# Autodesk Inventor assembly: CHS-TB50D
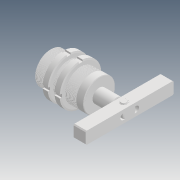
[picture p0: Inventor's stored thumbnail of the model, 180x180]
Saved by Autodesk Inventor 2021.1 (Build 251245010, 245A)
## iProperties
Created: 2019-04
Part Number: CHS-TB50D
Description: STEP AP203
Document SubType Name: Assembly
Designer: user
Title: chs-tb50d_asm.STEP
Revision Number: ÈÎºÎ
Sending System: SolidWorks 2017
Preprocessor: SwSTEP 2.0
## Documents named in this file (7)
- D:\Vault_2016\Projekty\Clamptek\Hydraulic\CHS\CHS-50\Inventor\CHS-TB50D\CHS-TB50D.iam
- D:\Vault_2016\Projekty\Clamptek\Hydraulic\CHS\CHS-50\Inventor\CHS-TB50D\CHS-TB50BT.ipt
- D:\Vault_2016\Projekty\Clamptek\Hydraulic\CHS\CHS-50\Inventor\CHS-TB50D\CHS-TB50LM.ipt
- D:\Vault_2016\Projekty\Clamptek\Hydraulic\CHS\CHS-50\Inventor\CHS-TB50D\CHS-50DHSG_2_1.ipt
- D:\Vault_2016\Projekty\Clamptek\Hydraulic\CHS\CHS-50\Inventor\CHS-TB50D\CHS-50DYB_3.ipt
- D:\Vault_2016\Projekty\Clamptek\Hydraulic\CHS\CHS-50\Inventor\CHS-TB50D\ÖáÓÃµ²È¦.ipt
- D:\Vault_2016\Projekty\Clamptek\Hydraulic\CHS\CHS-50\Inventor\CHS-TB50D\Ïú.ipt
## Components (8 placed, 8 different names)
1. CHS-TB50BT_1
2. CHS-TB50LM_2
3. CHS-TB50LM_3
4. CHS-50DHSG_2_1_4
5. CHS-50DYB_3_5
6. ÖáÓÃµ²È¦_6
7. Ïú_7
8. ÖáÓÃµ²È¦_8
